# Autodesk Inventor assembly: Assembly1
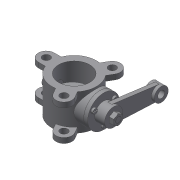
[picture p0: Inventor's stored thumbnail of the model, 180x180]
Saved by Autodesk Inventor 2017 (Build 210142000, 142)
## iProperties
Created: 2016-07
Part Number: Assembly1
Document SubType Name: Assembly
Designer: Sandeep
Author: Sandeep
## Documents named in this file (10)
- D:\KAVITA\Autodesk Inventor_2017_Project\Part's File\Inventor_2016_tut\c09_Inv_tut_2016\c09_tut01_inv\Butterfly Valve\OldVersions\Assembly1.iam
- D:\KAVITA\Autodesk Inventor_2017_Project\Part's File\Inventor_2016_tut\c09_Inv_tut_2016\c09_tut01_inv\Butterfly Valve\Body.ipt
- D:\KAVITA\Autodesk Inventor_2017_Project\Part's File\Inventor_2016_tut\c09_Inv_tut_2016\c09_tut01_inv\Butterfly Valve\shaft1.ipt
- D:\KAVITA\Autodesk Inventor_2017_Project\Part's File\Inventor_2016_tut\c09_Inv_tut_2016\c09_tut01_inv\Butterfly Valve\Retainer.ipt
- D:\KAVITA\Autodesk Inventor_2017_Project\Part's File\Inventor_2016_tut\c09_Inv_tut_2016\c09_tut01_inv\Butterfly Valve\Arm1.ipt
- D:\KAVITA\Autodesk Inventor_2017_Project\Part's File\Inventor_2016_tut\c09_Inv_tut_2016\c09_tut01_inv\Butterfly Valve\Plate.ipt
- D:\KAVITA\Autodesk Inventor_2017_Project\Part's File\Inventor_2016_tut\c09_Inv_tut_2016\c09_tut01_inv\Butterfly Valve\Screw.ipt
- D:\KAVITA\Autodesk Inventor_2017_Project\Part's File\Inventor_2016_tut\c09_Inv_tut_2016\c09_tut01_inv\Butterfly Valve\Parallel key.ipt
- D:\KAVITA\Autodesk Inventor_2017_Project\Part's File\Inventor_2016_tut\c09_Inv_tut_2016\c09_tut01_inv\Butterfly Valve\scew1.ipt
- D:\KAVITA\Autodesk Inventor_2017_Project\Part's File\Inventor_2016_tut\c09_Inv_tut_2016\c09_tut01_inv\Butterfly Valve\Nut.ipt
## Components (12 placed, 9 different names)
1. Body:1 — Insert:1, Insert:2, Insert:3, Angle:2
2. shaft1:1 — Insert:1, Angle:1, Angle:2, Insert:5, Insert:6, Mate:3, Insert:13
3. Retainer:1 — Insert:2, Insert:3, Insert:7, Insert:8, Insert:9, Insert:12
4. Arm1:1 — Angle:1, Insert:12, Mate:1, Mate:2
5. Plate:1 — Insert:5, Insert:6, Insert:10, Insert:11
6. Screw:1 — Insert:9
7. Screw:2 — Insert:8
8. Screw:3 — Insert:7
9. Parallel key:1 — Mate:1, Mate:2, Mate:3
10. scew1:1 — Insert:10
11. scew1:2 — Insert:11
12. Nut:1 — Insert:13
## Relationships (17: Insert 12, Mate 3, Angle 2)
- Insert:1: Body:1 ↔ shaft1:1
- Insert:2: Body:1 ↔ Retainer:1
- Insert:3: Body:1 ↔ Retainer:1
- Angle:1: shaft1:1 ↔ Arm1:1
- Angle:2: Body:1 ↔ shaft1:1
- Insert:5: shaft1:1 ↔ Plate:1
- Insert:6: shaft1:1 ↔ Plate:1
- Insert:7: Retainer:1 ↔ Screw:3
- Insert:8: Retainer:1 ↔ Screw:2
- Insert:9: Retainer:1 ↔ Screw:1
- Insert:10: Plate:1 ↔ scew1:1
- Insert:11: Plate:1 ↔ scew1:2
- Insert:12: Retainer:1 ↔ Arm1:1
- Mate:1: Arm1:1 ↔ Parallel key:1
- Mate:2: Arm1:1 ↔ Parallel key:1
- Mate:3: shaft1:1 ↔ Parallel key:1
- Insert:13: shaft1:1 ↔ Nut:1
